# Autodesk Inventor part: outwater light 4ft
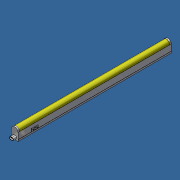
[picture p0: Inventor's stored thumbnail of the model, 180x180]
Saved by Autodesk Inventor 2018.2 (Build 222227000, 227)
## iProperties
Created: 2017-10
Part Number: outwater light 4ft
Material: Generic
Document SubType Name: Modeling
Designer: Admin
Density: 1 g/cm^3
Appearance: Snow
Author: Admin
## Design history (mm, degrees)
sketch "Sketch1"
  geometry: L1 (11, 0)-(-11, 0); L2 (-11, 0)-(-11, -25.332); L3 (-11, -25.332)-(11, -25.332); L4 (11, -25.332)-(11, 0); L5 (-11.5, -20.332)-(11.5, -20.332); L6 (11.5, -20.332)-(11.5, -25.332); L7 (11.5, -25.332)-(-11.5, -25.332); L8 (-11.5, -25.332)-(-11.5, -20.332); C1 r 10.668 at (0, 0); 4 further points
  constraints: 16 end point, 4 coincident, 4 parallel, 3 midpoint, 2 horizontal, 2 perpendicular, 1 centre point
  dimensions: "d0" = 21.336 diameter of C1; "d1" = 22 distance of L2.end L3.end; "d2" = 36 dimension on C1 L3; "d5" = 0 distance between parallel lines of L3 L7; "d6" = 23 distance of L5.start L5.end; "d7" = 5 distance between parallel lines of L3 L5
extrude "Extrusion1" new body sketch "Sketch1" stored distance "d3" = 493; taper "d4" = 0 deg
sketch "Sketch2"
  geometry: L1 (-11, 0)-(-10.668, 0) reference; L2 (-11, -20.332)-(-11, 0) reference; L3 (11.5, -25.332)-(-11.5, -25.332) reference; L4 (11, 0)-(11, -20.332) reference; L5 (10.668, 0)-(11, 0) reference; L6 (-11.5, -25.332)-(-11.5, -20.332) reference; L7 (11.5, -20.332)-(11.5, -25.332) reference; L8 (11, -20.332)-(11.5, -20.332) reference; L9 (-11, 0)-(-10.668, 0) reference; L10 (-11, -20.332)-(-11, 0) reference; L11 (-11.5, -20.332)-(-11, -20.332) reference; L12 (-11.5, -25.332)-(-11.5, -20.332) reference; L13 (11.5, -25.332)-(-11.5, -25.332) reference; L14 (11.5, -20.332)-(11.5, -25.332) reference; L15 (11, -20.332)-(11.5, -20.332) reference; L16 (11, 0)-(11, -20.332) reference; L17 (10.668, 0)-(11, 0) reference; A1 r 10.668 centre (0, 0) between (10.668, 0) and (-10.668, 0) reference; A2 r 11 centre (0, 0) between (11, 0) and (-11, 0); A3 r 10.668 centre (0, 0) between (10.668, 0) and (-10.668, 0) reference
  constraints: 2 end point, 2 point on circle, 1 centre point, 1 coincident, 1 tangent
extrude "Extrusion2" join sketch "Sketch2" distance "d8" = 5; taper "d9" = 0 deg
mirror "Mirror1"
sketch "Sketch3"
  geometry: L1 (-2.2, -12.732)-(2.2, -12.732); L2 (2.2, -21.932)-(-2.2, -21.932); L3 (2.2, -13.932)-(-2.2, -13.932); L4 (-2.2, -20.732)-(2.2, -20.732); L5 (-11.5, -25.332)-(11.5, -25.332) reference; A1 r 4.6 centre (-2.2, -17.332) between (-2.2, -12.732) and (-2.2, -21.932); A2 r 4.6 centre (2.2, -17.332) between (2.2, -21.932) and (2.2, -12.732); A3 r 3.4 centre (-2.2, -17.332) between (-2.2, -13.932) and (-2.2, -20.732); A4 r 3.4 centre (2.2, -17.332) between (2.2, -20.732) and (2.2, -13.932); 2 further points
  constraints: 8 end point, 8 point on circle, 4 centre point, 2 midpoint, 2 parallel, 2 tangent, 1 equal radius, 1 horizontal, 1 horizontal alignment, 1 vertical alignment, 3 other
  dimensions: "d11" = 9.2 distance between parallel lines of L2 L1; "d12" = 13.6 dimension on A2 A1; "d13" = 1.2 distance between parallel lines of L3 L1; "d22" = 8 distance from line of A2.centre L5
extrude "Extrusion3" join sketch "Sketch3" distance "d14" = 10.8; taper "d15" = 0 deg
sketch "Sketch4"
  geometry: C1 r 0.75 at (-2.2, -17.332); C2 r 0.75 at (2.2, -17.332); A1 r 3.4 centre (2.2, -17.332) between (2.2, -20.732) and (2.2, -13.932) reference; A2 r 3.4 centre (-2.2, -17.332) between (-2.2, -13.932) and (-2.2, -20.732) reference; 1 further point
  constraints: 2 centre point, 2 coincident, 1 equal radius
  dimensions: "d16" = 1.5 diameter of C2
extrude "Extrusion4" join sketch "Sketch4" distance "d17" = 9.4; taper "d18" = 0 deg
fillet "Fillet1" dims "d19" = 0.75
sketch "Sketch5"
  geometry: L1 (-2.2, -20.732)-(2.2, -20.732) reference; L2 (2.2, -13.932)-(-2.2, -13.932) reference; L3 (2.2, -21.932)-(-2.2, -21.932) reference; L4 (-2.2, -12.732)-(2.2, -12.732) reference; C1 r 0.75 at (2.2, -17.332) reference; C2 r 0.75 at (-2.2, -17.332) reference; A1 r 3.4 centre (-2.2, -17.332) between (-2.2, -13.932) and (-2.2, -20.732) reference; A2 r 3.4 centre (2.2, -17.332) between (2.2, -20.732) and (2.2, -13.932) reference; A3 r 4.6 centre (2.2, -17.332) between (2.2, -21.932) and (2.2, -12.732) reference; A4 r 4.6 centre (-2.2, -17.332) between (-2.2, -12.732) and (-2.2, -21.932) reference
extrude "Extrusion5" cut sketch "Sketch5" distance "d20" = 10.8; taper "d21" = 0 deg
sketch "Sketch6"
  geometry: L1 (503, 0)-(0, 0) reference; L2 (0, 0)-(0, 20.332) reference; L3 (44, 10)-(65, 10); L4 (65, 10)-(65, 0.5); L5 (65, 0.5)-(44, 0.5); L6 (44, 0.5)-(44, 10); L7 (49.75, 8)-(59.25, 8); L8 (59.25, 2.5)-(49.75, 2.5); A1 r 2.75 centre (49.75, 5.25) between (49.75, 8) and (49.75, 2.5); A2 r 2.75 centre (59.25, 5.25) between (59.25, 2.5) and (59.25, 8); 4 further points
  constraints: 12 end point, 4 point on circle, 3 midpoint, 3 parallel, 2 centre point, 2 horizontal, 2 horizontal alignment, 2 tangent, 1 equal radius, 1 perpendicular, 1 vertical alignment
  dimensions: "d23" = 9.5 distance of L5.end L3.start; "d24" = 0.5 distance between parallel lines of L5 L1; "d25" = 21 distance of L3.start L3.end; "d26" = 44 distance between parallel lines of L6 L2; "d27" = 5.5 distance between parallel lines of L8 L7; "d28" = 15 dimension on A2 A1
extrude "Extrusion6" join sketch "Sketch6" distance "d29" = 1.55; taper "d30" = 0 deg
workplane "Work Plane1"
sketch "Sketch7"
  geometry: L1 (0, -5.75)-(0, 15.25) reference; L2 (0, -2.25)-(3.5, -2.25); L3 (3.5, -2.25)-(3.5, 11.75); L4 (3.5, 11.75)-(0, 11.75); L5 (0, 11.75)-(0, -2.25); L6 (1.55, 0)-(1.55, -2.75) reference; L7 (1.55, 12.25)-(1.55, 9.5) reference; A1 r 12.964 centre (14.411, 4.75) between (3.5, 11.75) and (3.5, -2.25); 1 further point
  constraints: 8 end point, 2 parallel, 2 point on circle, 1 centre point, 1 horizontal, 1 perpendicular, 1 point on line
  dimensions: "d31" = 0.5 distance from line of L6.end L2; "d32" = 0.5 distance from line of L4 L7.start; "d33" = 3.5 distance between parallel lines of L3 L1
extrude "Extrusion7" join sketch "Sketch7" stored distance "d34" = 4; taper "d35" = 0 deg
fillet "Fillet2" dims "d36" = 0.75
body "Solid1"
node "Projected Loop1"
node "Projected Loop2"
node "Projected Loop3"
node "Projected Loop4"
